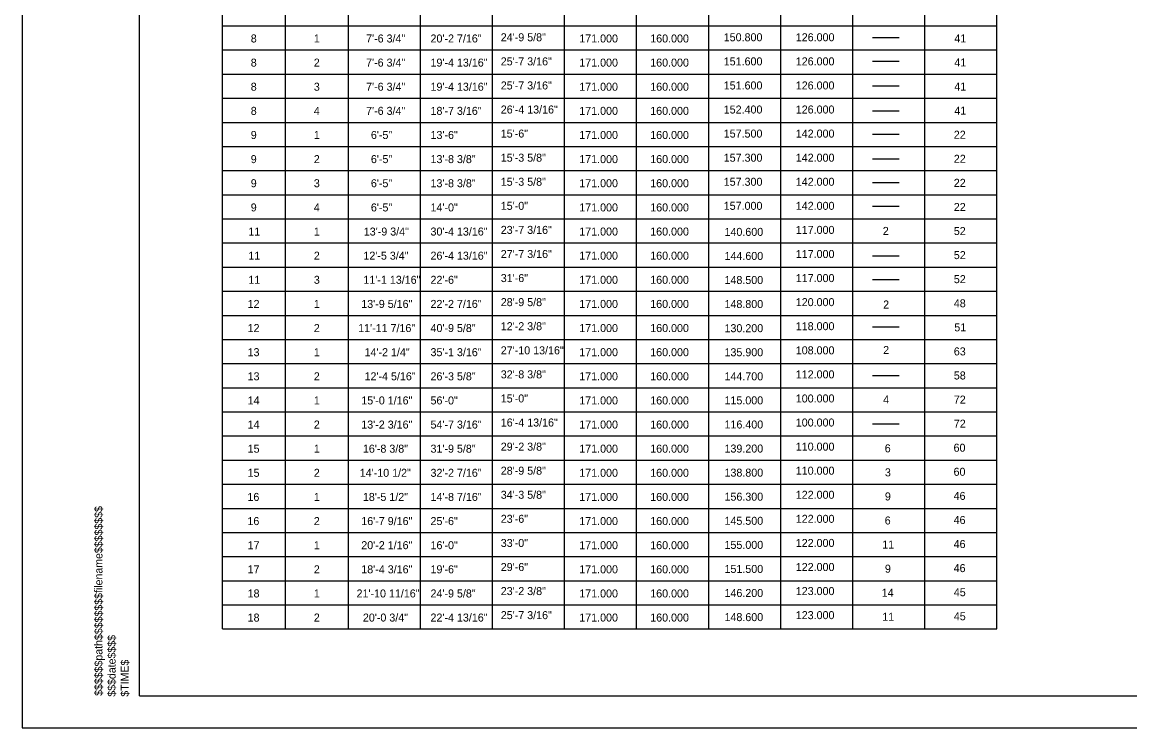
# Model space of a CAD drawing. Extents: x -133.1 to -97, y -1.7 to 20.3.
# Drawn here: x -133.14 to -115.84, y -1.69 to 9.34 of the extents above; entities that cross this region are included whole.
import ezdxf

# ---------------------------------------------------------------- set-up
doc = ezdxf.new("R2010")
doc.units = 0
for name, color, linetype in [('BR_AUTO DIMENSION', 7, 'Continuous'), ('BR_BORDER LINES', 7, 'Continuous'), ('BR_TABLE LINES', 7, 'Continuous'), ('BR_TEXT', 7, 'Continuous'), ('Level 31', 7, 'Continuous'), ('RD_SHT_ID', 7, 'Continuous')]:
    doc.layers.add(name, color=color, linetype=linetype)

msp = doc.modelspace()

# ---------------------------------------------------------------- linework, layer by layer
at = {"layer": 'BR_AUTO DIMENSION'}
for p, q in [((-120.17, -0.146), (-120.17, 18.753)), ((-119.045, -0.146), (-119.045, 18.753))]:
    msp.add_line(p, q, dxfattribs=at)
at = {"layer": 'BR_BORDER LINES'}
for q in [(-131.308, 19.809), (-97.642, -1.191)]:
    msp.add_line((-131.308, -1.191), q, dxfattribs=at)
at = {"layer": 'BR_TABLE LINES'}
for p, q in [((-130.014, -0.146), (-130.014, 19.253)), ((-117.92, -0.146), (-117.92, 19.253)), ((-129.03, -0.146), (-129.029, 18.753)), ((-128.045, -0.146), (-128.045, 18.753)), ((-126.92, -0.146), (-126.92, 18.753)), ((-125.795, -0.146), (-125.795, 18.753)), ((-124.67, -0.146), (-124.67, 18.753)), ((-123.545, -0.146), (-123.545, 18.753)), ((-122.42, -0.146), (-122.42, 18.753)), ((-121.295, -0.146), (-121.295, 18.753)), ((-120.17, -0.146), (-120.17, 18.753)), ((-119.045, -0.146), (-119.045, 18.753)), ((-130.014, 9.28), (-117.92, 9.28)), ((-130.014, 8.903), (-117.92, 8.903)), ((-130.014, 8.526), (-117.92, 8.526)), ((-130.014, 8.148), (-117.92, 8.148)), ((-130.014, 7.771), (-117.92, 7.771)), ((-130.014, 7.394), (-117.92, 7.394)), ((-130.014, 7.017), (-117.92, 7.017)), ((-130.014, 6.64), (-117.92, 6.64)), ((-130.014, 6.263), (-117.92, 6.263)), ((-130.014, 5.886), (-117.92, 5.886)), ((-130.014, 5.509), (-117.92, 5.509)), ((-130.014, 5.132), (-117.92, 5.132)), ((-130.014, 4.755), (-117.92, 4.755)), ((-130.014, 4.378), (-117.92, 4.378)), ((-130.014, 4.001), (-117.92, 4.001)), ((-130.014, 3.624), (-117.92, 3.624)), ((-130.014, 3.247), (-117.92, 3.247)), ((-130.014, 2.87), (-117.92, 2.87)), ((-130.014, 2.493), (-117.92, 2.493)), ((-130.014, 2.116), (-117.92, 2.116)), ((-130.014, 1.739), (-117.92, 1.739)), ((-130.014, 1.362), (-117.92, 1.362)), ((-130.014, 0.985), (-117.92, 0.985)), ((-130.014, 0.608), (-117.92, 0.608)), ((-130.014, 0.231), (-117.92, 0.231)), ((-130.014, -0.146), (-117.92, -0.146))]:
    msp.add_line(p, q, dxfattribs=at)
at = {"layer": 'BR_TEXT'}
for p, q in [((-119.863, 9.097), (-119.445, 9.097)), ((-119.863, 8.728), (-119.445, 8.728)), ((-119.863, 8.34), (-119.445, 8.34)), ((-119.863, 7.952), (-119.445, 7.952)), ((-119.863, 7.584), (-119.445, 7.584)), ((-119.863, 7.2), (-119.445, 7.2)), ((-119.863, 6.83), (-119.445, 6.83)), ((-119.863, 6.46), (-119.445, 6.46)), ((-119.863, 5.684), (-119.445, 5.684)), ((-119.863, 5.317), (-119.445, 5.317)), ((-119.863, 4.574), (-119.445, 4.574)), ((-119.863, 3.817), (-119.445, 3.817)), ((-119.863, 3.061), (-119.445, 3.061))]:
    msp.add_line(p, q, dxfattribs=at)
at = {"layer": 'Level 31'}
msp.add_lwpolyline([(-133.141, -1.691), (-97.141, -1.691), (-97.141, 20.309), (-133.141, 20.309)], close=True, dxfattribs=at)

# ---------------------------------------------------------------- texts
at = {"layer": 'BR_TEXT'}
for s, p in [('24\'-9 5/8"', (-125.667, 9.038)), ('8', (-129.571, 9.019)), ('1', (-128.586, 9.019)), ('7\'-6 3/4"', (-127.77, 9.019)), ('20\'-2 7/16"', (-126.764, 9.019)), ('171.000', (-124.441, 9.019)), ('160.000', (-123.333, 9.019)), ('150.800', (-122.185, 9.038)), ('126.000', (-121.06, 9.038)), ('41', (-118.584, 9.02)), ('8', (-129.571, 8.642)), ('2', (-128.586, 8.642)), ('7\'-6 3/4"', (-127.77, 8.642)), ('19\'-4 13/16"', (-126.764, 8.642)), ('25\'-7 3/16"', (-125.667, 8.661)), ('171.000', (-124.441, 8.642)), ('160.000', (-123.333, 8.642)), ('151.600', (-122.185, 8.661)), ('126.000', (-121.06, 8.661)), ('41', (-118.584, 8.644)), ('8', (-129.571, 8.265)), ('3', (-128.586, 8.265)), ('7\'-6 3/4"', (-127.77, 8.265)), ('19\'-4 13/16"', (-126.764, 8.265)), ('25\'-7 3/16"', (-125.667, 8.285)), ('171.000', (-124.441, 8.265)), ('160.000', (-123.333, 8.265)), ('151.600', (-122.185, 8.285)), ('126.000', (-121.06, 8.285)), ('41', (-118.584, 8.268)), ('8', (-129.571, 7.888)), ('4', (-128.586, 7.888)), ('7\'-6 3/4"', (-127.77, 7.888)), ('18\'-7 3/16"', (-126.764, 7.888)), ('26\'-4 13/16"', (-125.667, 7.909)), ('171.000', (-124.441, 7.888)), ('160.000', (-123.333, 7.888)), ('152.400', (-122.185, 7.909)), ('126.000', (-121.06, 7.909)), ('41', (-118.584, 7.891)), ('9', (-129.571, 7.511)), ('1', (-128.586, 7.511)), ('6\'-5"', (-127.695, 7.511)), ('13\'-6"', (-126.764, 7.511)), ('15\'-6"', (-125.667, 7.533)), ('171.000', (-124.441, 7.511)), ('160.000', (-123.333, 7.511)), ('157.500', (-122.185, 7.533)), ('142.000', (-121.06, 7.533)), ('22', (-118.592, 7.515)), ('13\'-8 3/8"', (-126.764, 7.134)), ('15\'-3 5/8"', (-125.667, 7.156)), ('157.300', (-122.185, 7.156)), ('142.000', (-121.06, 7.156)), ('22', (-118.592, 7.139)), ('9', (-129.571, 7.134)), ('2', (-128.586, 7.134)), ('6\'-5"', (-127.695, 7.134)), ('171.000', (-124.441, 7.134)), ('160.000', (-123.333, 7.134)), ('9', (-129.571, 6.757)), ('3', (-128.586, 6.757)), ('6\'-5"', (-127.695, 6.757)), ('13\'-8 3/8"', (-126.764, 6.757)), ('15\'-3 5/8"', (-125.667, 6.78)), ('171.000', (-124.441, 6.757)), ('160.000', (-123.333, 6.757)), ('157.300', (-122.185, 6.78)), ('142.000', (-121.06, 6.78)), ('22', (-118.592, 6.763)), ('9', (-129.571, 6.379)), ('4', (-128.586, 6.379)), ('6\'-5"', (-127.695, 6.379)), ('14\'-0"', (-126.764, 6.379)), ('15\'-0"', (-125.667, 6.404)), ('171.000', (-124.441, 6.379)), ('160.000', (-123.333, 6.379)), ('157.000', (-122.185, 6.404)), ('142.000', (-121.06, 6.404)), ('22', (-118.592, 6.386)), ('11', (-129.608, 6.002)), ('1', (-128.586, 6.002)), ('13\'-9 3/4"', (-127.806, 6.002)), ('30\'-4 13/16"', (-126.764, 6.002)), ('23\'-7 3/16"', (-125.667, 6.028)), ('171.000', (-124.441, 6.002)), ('160.000', (-123.333, 6.002)), ('140.600', (-122.173, 5.997)), ('117.000', (-121.06, 6.028)), ('2', (-119.701, 6.012)), ('52', (-118.592, 6.01)), ('11', (-129.608, 5.625)), ('2', (-128.586, 5.625)), ('12\'-5 3/4"', (-127.812, 5.625)), ('26\'-4 13/16"', (-126.764, 5.625)), ('27\'-7 3/16"', (-125.667, 5.651)), ('171.000', (-124.441, 5.625)), ('160.000', (-123.333, 5.625)), ('144.600', (-122.173, 5.621)), ('117.000', (-121.06, 5.651)), ('52', (-118.592, 5.634)), ('11', (-129.608, 5.248)), ('3', (-128.586, 5.248)), ('11\'-1 13/16"', (-127.812, 5.248)), ('22\'-6"', (-126.764, 5.248)), ('31\'-6"', (-125.667, 5.275)), ('171.000', (-124.441, 5.248)), ('160.000', (-123.333, 5.248)), ('148.500', (-122.173, 5.245)), ('117.000', (-121.06, 5.275)), ('52', (-118.592, 5.258)), ('28\'-9 5/8"', (-125.667, 4.899)), ('120.000', (-121.06, 4.899)), ('12', (-129.62, 4.871)), ('1', (-128.586, 4.871)), ('13\'-9 5/16"', (-127.845, 4.871)), ('22\'-2 7/16"', (-126.764, 4.871)), ('171.000', (-124.441, 4.871)), ('160.000', (-123.333, 4.871)), ('148.800', (-122.173, 4.869)), ('2', (-119.695, 4.862)), ('48', (-118.592, 4.881)), ('12', (-129.62, 4.494)), ('2', (-128.586, 4.494)), ('11\'-11 7/16"', (-127.894, 4.494)), ('40\'-9 5/8"', (-126.764, 4.494)), ('12\'-2 3/8"', (-125.667, 4.523)), ('171.000', (-124.441, 4.494)), ('160.000', (-123.333, 4.494)), ('130.200', (-122.173, 4.492)), ('118.000', (-121.06, 4.523)), ('51', (-118.584, 4.505)), ('13', (-129.62, 4.117)), ('1', (-128.586, 4.117)), ('14\'-2 1/4"', (-127.794, 4.117)), ('35\'-1 3/16"', (-126.764, 4.117)), ('27\'-10 13/16"', (-125.667, 4.146)), ('171.000', (-124.441, 4.117)), ('160.000', (-123.333, 4.117)), ('135.900', (-122.173, 4.116)), ('108.000', (-121.06, 4.146)), ('2', (-119.695, 4.151)), ('63', (-118.592, 4.129)), ('13', (-129.62, 3.74)), ('2', (-128.586, 3.74)), ('12\'-4 5/16"', (-127.794, 3.74)), ('26\'-3 5/8"', (-126.764, 3.74)), ('32\'-8 3/8"', (-125.667, 3.77)), ('171.000', (-124.441, 3.74)), ('160.000', (-123.333, 3.74)), ('144.700', (-122.173, 3.74)), ('112.000', (-121.06, 3.77)), ('58', (-118.592, 3.753)), ('14', (-129.62, 3.363)), ('1', (-128.586, 3.363)), ('15\'-0 1/16"', (-127.845, 3.363)), ('56\'-0"', (-126.764, 3.363)), ('15\'-0"', (-125.667, 3.394)), ('171.000', (-124.441, 3.363)), ('160.000', (-123.333, 3.363)), ('115.000', (-122.173, 3.364)), ('100.000', (-121.06, 3.394)), ('4', (-119.695, 3.378)), ('72', (-118.592, 3.376)), ('13\'-2 3/16"', (-127.845, 2.986)), ('54\'-7 3/16"', (-126.764, 2.986)), ('16\'-4 13/16"', (-125.667, 3.018)), ('116.400', (-122.173, 2.987)), ('100.000', (-121.06, 3.018)), ('72', (-118.592, 3)), ('14', (-129.62, 2.986)), ('2', (-128.586, 2.986)), ('171.000', (-124.441, 2.986)), ('160.000', (-123.333, 2.986)), ('29\'-2 3/8"', (-125.667, 2.641)), ('110.000', (-121.06, 2.641)), ('15', (-129.62, 2.609)), ('1', (-128.586, 2.609)), ('16\'-8 3/8"', (-127.82, 2.609)), ('31\'-9 5/8"', (-126.764, 2.609)), ('171.000', (-124.441, 2.609)), ('160.000', (-123.333, 2.609)), ('139.200', (-122.173, 2.611)), ('6', (-119.671, 2.615)), ('60', (-118.596, 2.624)), ('15', (-129.62, 2.232)), ('2', (-128.586, 2.232)), ('14\'-10 1/2"', (-127.869, 2.232)), ('32\'-2 7/16"', (-126.764, 2.232)), ('28\'-9 5/8"', (-125.667, 2.265)), ('171.000', (-124.441, 2.232)), ('160.000', (-123.333, 2.232)), ('138.800', (-122.173, 2.235)), ('110.000', (-121.06, 2.265)), ('3', (-119.668, 2.239)), ('60', (-118.596, 2.248)), ('16', (-129.623, 1.855)), ('1', (-128.586, 1.855)), ('18\'-5 1/2"', (-127.82, 1.855)), ('14\'-8 7/16"', (-126.764, 1.855)), ('34\'-3 5/8"', (-125.667, 1.889)), ('171.000', (-124.441, 1.855)), ('160.000', (-123.333, 1.855)), ('156.300', (-122.173, 1.859)), ('122.000', (-121.06, 1.889)), ('9', (-119.668, 1.863)), ('46', (-118.595, 1.871)), ('16', (-129.623, 1.478)), ('2', (-128.586, 1.478)), ('16\'-7 9/16"', (-127.845, 1.478)), ('25\'-6"', (-126.764, 1.478)), ('23\'-6"', (-125.667, 1.513)), ('171.000', (-124.441, 1.478)), ('160.000', (-123.333, 1.478)), ('145.500', (-122.173, 1.482)), ('122.000', (-121.06, 1.513)), ('6', (-119.671, 1.487)), ('46', (-118.595, 1.495)), ('17', (-129.62, 1.101)), ('1', (-128.586, 1.101)), ('20\'-2 1/16"', (-127.845, 1.101)), ('16\'-0"', (-126.764, 1.101)), ('33\'-0"', (-125.667, 1.136)), ('171.000', (-124.441, 1.101)), ('160.000', (-123.333, 1.101)), ('155.000', (-122.173, 1.106)), ('122.000', (-121.06, 1.136)), ('11', (-119.71, 1.11)), ('46', (-118.595, 1.119)), ('29\'-6"', (-125.667, 0.76)), ('122.000', (-121.06, 0.76)), ('46', (-118.595, 0.743)), ('17', (-129.62, 0.724)), ('2', (-128.586, 0.724)), ('18\'-4 3/16"', (-127.845, 0.724)), ('19\'-6"', (-126.764, 0.724)), ('171.000', (-124.441, 0.724)), ('160.000', (-123.333, 0.724)), ('151.500', (-122.173, 0.73)), ('9', (-119.668, 0.734)), ('18', (-129.62, 0.347)), ('1', (-128.586, 0.347)), ('21\'-10 11/16"', (-127.919, 0.347)), ('24\'-9 5/8"', (-126.764, 0.347)), ('23\'-2 3/8"', (-125.667, 0.384)), ('171.000', (-124.441, 0.347)), ('160.000', (-123.333, 0.347)), ('146.200', (-122.173, 0.354)), ('123.000', (-121.06, 0.384)), ('14', (-119.718, 0.358)), ('45', (-118.592, 0.366)), ('18', (-129.62, -0.03)), ('2', (-128.586, -0.03)), ('20\'-0 3/4"', (-127.82, -0.03)), ('22\'-4 13/16"', (-126.764, -0.03)), ('25\'-7 3/16"', (-125.667, 0.008)), ('171.000', (-124.441, -0.03)), ('160.000', (-123.333, -0.03)), ('148.600', (-122.173, -0.023)), ('123.000', (-121.06, 0.008)), ('11', (-119.71, -0.018)), ('45', (-118.592, -0.01))]:
    msp.add_text(s, height=0.125, rotation=360, dxfattribs=at).set_placement(p)
at = {"layer": 'RD_SHT_ID'}
for s, height, p in [('$$$$$$path$$$$$$$$filename$$$$$$$$', 0.12347, (-131.887, -1.191)), ('$$$date$$$$', 0.12347, (-131.682, -1.204)), ('$TIME$', 0.1235, (-131.477, -1.204))]:
    msp.add_text(s, height=height, rotation=90, dxfattribs=at).set_placement(p)

doc.saveas('drawing.dxf')
